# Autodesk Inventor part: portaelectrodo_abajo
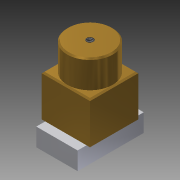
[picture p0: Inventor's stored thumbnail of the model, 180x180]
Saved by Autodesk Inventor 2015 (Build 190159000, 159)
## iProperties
Created: 2016-06
Part Number: portaelectrodo_abajo
Material: Genérico
Document SubType Name: Modeling
Designer: Diego
Density: 1 g/cm^3
Appearance: Valor por defecto
Author: Diego
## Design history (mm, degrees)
sketch "Boceto1"
  geometry: L1 (0, 0)-(30, 0); L2 (30, 0)-(30, 48); L3 (30, 48)-(0, 48); L4 (0, 48)-(0, 0)
  constraints: 8 end point, 2 parallel, 1 horizontal, 1 perpendicular
  dimensions: "d0" = 30 distance of L3.end L2.end; "d1" = 48 distance of L2.end L1.end
extrude "Extrusión1" new body sketch "Boceto1" distance "d2" = 13; taper "d3" = 0 deg
sketch "Boceto2"
  geometry: C1 r 12.5 at (15, 24); 1 further point
  constraints: 1 centre point
  dimensions: "d4" = 25 diameter of C1
extrude "Extrusión2" join sketch "Boceto2" distance "d5" = 30; taper "d6" = 0 deg
sketch "Boceto3"
  geometry: L1 (15, 24)-(-2.5, 24); L2 (-2.5, 24)-(32.5, 24); L3 (32.5, 24)-(32.5, 41.5); L4 (32.5, 41.5)-(-2.5, 41.5); L5 (-2.5, 41.5)-(-2.5, 6.5); L6 (-2.5, 6.5)-(32.5, 6.5); L7 (32.5, 6.5)-(32.5, 41.5); C1 r 12.5 at (15, 24) reference; 1 further point
  constraints: 14 end point, 2 horizontal, 2 parallel, 2 perpendicular, 1 point on line
  dimensions: "d7" = 17.5 distance of L1.start L1.end; "d8" = 35 distance of L1.end L2.end; "d9" = 17.5 distance of L2.end L3.end; "d10" = 35 distance of L6.end L5.end; "d11" = 35 distance of L5.end L4.end
extrude "Extrusión3" join sketch "Boceto3" distance "d12" = 30; taper "d13" = 0 deg
sketch "Boceto4"
  geometry: C1 r 16.5 at (15, 24); 1 further point
  constraints: 1 centre point
  dimensions: "d14" = 33 diameter of C1
extrude "Extrusión4" join sketch "Boceto4" distance "d15" = 20; taper "d16" = 0 deg
chamfer "Chaflán1" distance "d17" = 1; stored, may be unused: second distance "d18" = 2, angle "d19" = 45 deg
chamfer "Chaflán2" distance "d20" = 1; stored, may be unused: second distance "d21" = 2, angle "d22" = 45 deg
sketch "Boceto5"
  geometry: 2 further points
hole "Agujero1" sketch "Boceto5" at (0, 0) diameter "d23" = 4.917; stored, may be unused: countersink angle "d27" = 90 deg, drill point angle "d29" = 118 deg; dims "d24" = 4, "d25" = 4, "d26" = 2, "d28" = 5
node "Sólido1"
